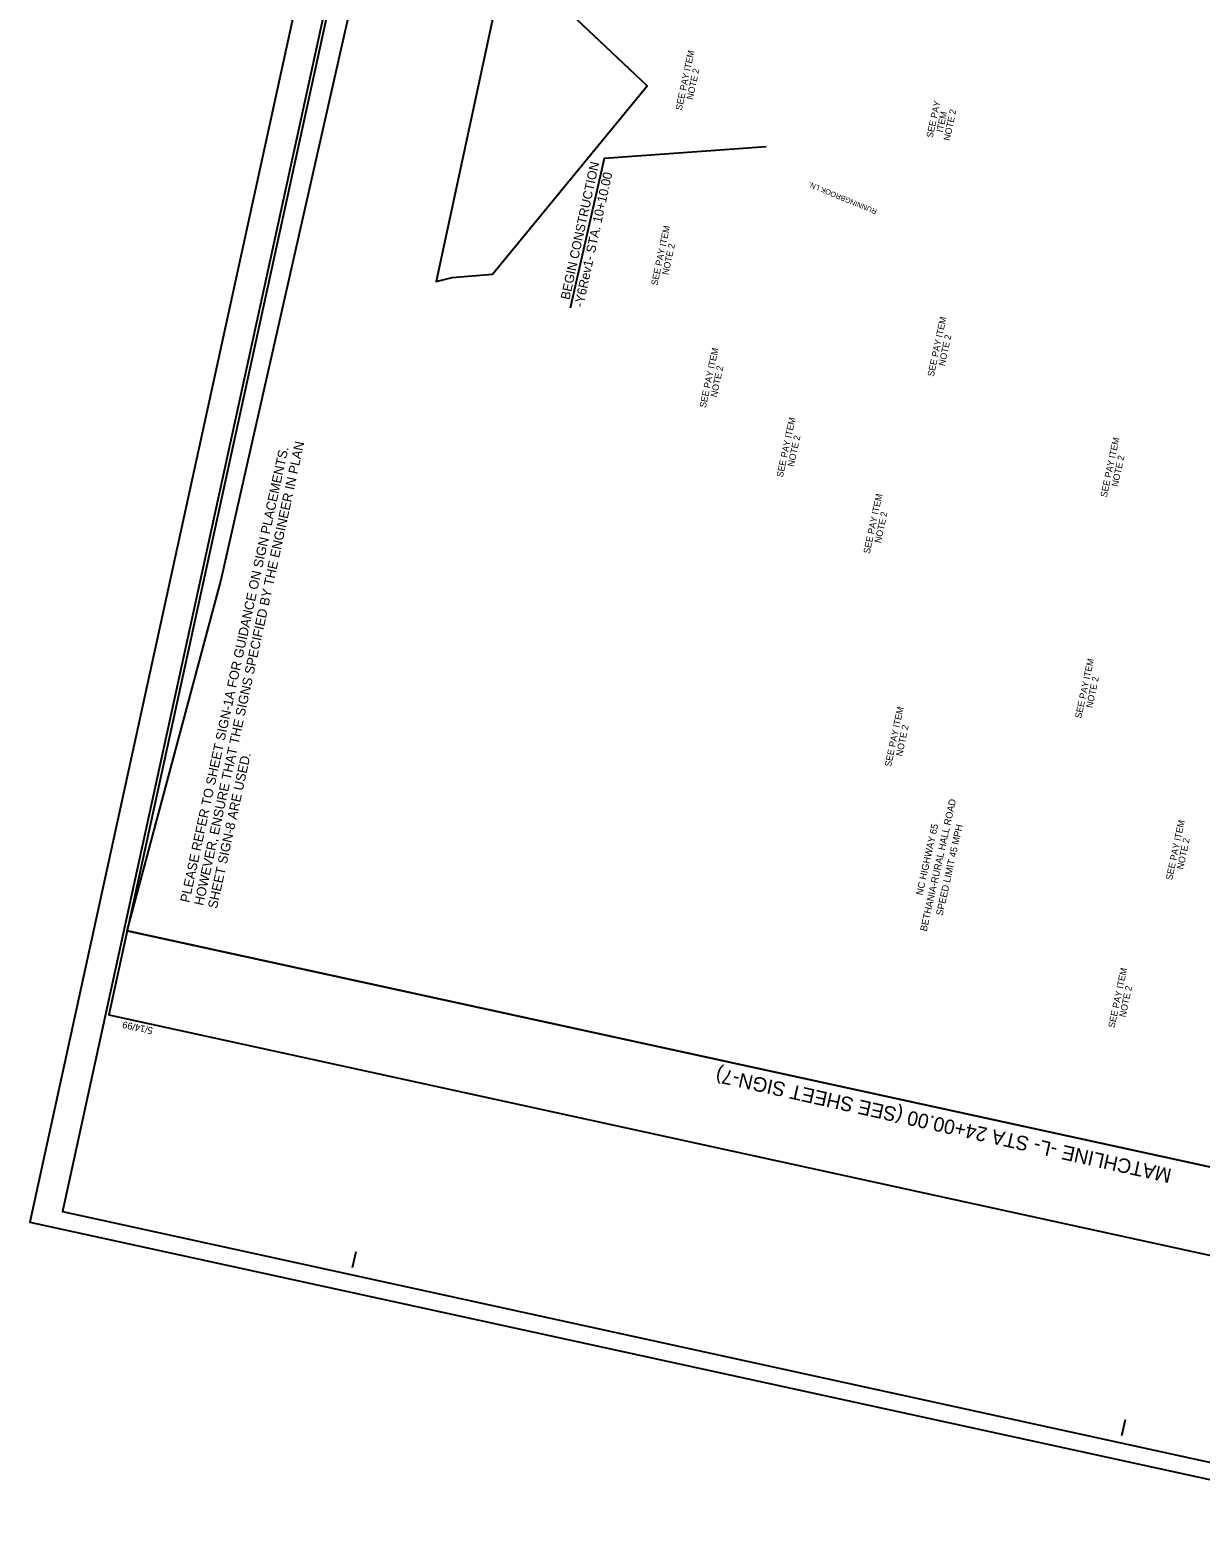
# Model space of a CAD drawing. Extents: x 1615829 to 1617263, y 900664 to 902544.
# Drawn here: x 1615829 to 1616720, y 900664 to 901807 of the extents above; entities that cross this region are included whole.
import ezdxf

# ---------------------------------------------------------------- set-up
doc = ezdxf.new("R2010")
doc.units = 0
for name, color, linetype in [('Default', 7, 'Continuous'), ('Exist PHM ROW shape', 7, 'Continuous'), ('Prop Conc Drive Radius Type', 7, 'Continuous'), ('Prop Conc Island Cover', 7, 'Continuous'), ('Prop Dimension Text', 7, 'Continuous'), ('Prop Lane Arrow CELL', 7, 'Continuous'), ('Prop PHM Concrete Structures Shape', 7, 'Continuous'), ('Prop Shade Medium', 7, 'Continuous'), ('Scratch_Level_2', 7, 'Continuous')]:
    doc.layers.add(name, color=color, linetype=linetype)

msp = doc.modelspace()

# ---------------------------------------------------------------- linework, layer by layer
at = {"layer": 'Exist PHM ROW shape'}
msp.add_lwpolyline([(1616240.6, 901594.9), (1616266.7, 901709), (1616389.9, 901717.9)], dxfattribs=at)
at = {"layer": 'Prop Conc Drive Radius Type'}
msp.add_lwpolyline([(1616850.4, 902379.9), (1617227.5, 902296.2), (1617121.4, 901790.4), (1617088.2, 901641.8), (1617042.4, 901522.3), (1617032.3, 901430.6), (1617021.4, 901334.4), (1616928.8, 900896.8), (1615902.8, 901120.3), (1615974.3, 901386.7), (1616087.7, 901888.9), (1616145.5, 901879.2), (1616184.1, 901827.5), (1616138.4, 901615), (1616150.6, 901618.1), (1616181.3, 901620.7), (1616299.2, 901764.2), (1616120.1, 901933.3), (1616161.3, 902112.5), (1616179.7, 902310.4), (1616356.3, 902284.9), (1616372.4, 902359)], close=True, dxfattribs=at)
at = {"layer": 'Prop Dimension Text'}
msp.add_line((1615902.8, 901120.3), (1616928.8, 900896.8), dxfattribs=at)
at = {"layer": 'Prop PHM Concrete Structures Shape'}
for p, q in [((1615889.1, 901057.4), (1615889.1, 901057.4)), ((1616074.6, 900863.9), (1616077.3, 900876.1)), ((1616660.8, 900735.9), (1616663.5, 900748.1))]:
    msp.add_line(p, q, dxfattribs=at)
msp.add_lwpolyline([(1616208.8, 902521.9), (1615888.9, 901056.4), (1616914.7, 900832.5), (1617234.6, 902298)], close=True, dxfattribs=at)
at = {"layer": 'Prop Shade Medium'}
msp.add_lwpolyline([(1616188, 902543.8), (1615828.8, 900898.6), (1616903.5, 900664), (1617262.7, 902309.2)], close=True, dxfattribs=at)
at = {"layer": 'Scratch_Level_2'}
msp.add_lwpolyline([(1616209, 902534.7), (1615853.6, 900906.5), (1616884.4, 900681.5), (1617239.8, 902309.6)], close=True, dxfattribs=at)

# ---------------------------------------------------------------- texts
at = {"layer": 'Default'}
for s, height, rotation, p in [('SEE PAY ITEM', 5, 77.9223, (1616325.5, 901745.2)), ('NOTE 2', 5, 77.9223, (1616333.9, 901753.2)), ('SEE PAY', 5, 77.9223, (1616516.7, 901724.2)), ('ITEM', 5, 77.9223, (1616524.3, 901728.4)), ('NOTE 2', 5, 77.9223, (1616529.7, 901722)), ('SEE PAY ITEM', 5, 77.9223, (1616306.9, 901611.7)), ('NOTE 2', 5, 77.9223, (1616315.3, 901619.8)), ('SEE PAY ITEM', 5, 77.9223, (1616517.5, 901542.3)), ('NOTE 2', 5, 77.9223, (1616525.9, 901550.4)), ('SEE PAY ITEM', 5, 77.9223, (1616343.8, 901518.5)), ('NOTE 2', 5, 77.9223, (1616352.2, 901526.6)), ('SEE PAY ITEM', 5, 77.9223, (1616402.5, 901465.6)), ('NOTE 2', 5, 77.9223, (1616410.9, 901473.7)), ('PLEASE REFER TO SHEET SIGN-1A FOR GUIDANCE ON SIGN PLACEMENTS.', 7.199, 77.6862, (1615950.2, 901141.5)), ('HOWEVER, ENSURE THAT THE SIGNS SPECIFIED BY THE ENGINEER IN PLAN', 7.199, 77.6862, (1615960.8, 901139.2)), ('SEE PAY ITEM', 5, 77.9223, (1616649.3, 901450.3)), ('NOTE 2', 5, 77.9223, (1616657.8, 901458.4)), ('SEE PAY ITEM', 5, 77.9223, (1616468.7, 901407.4)), ('NOTE 2', 5, 77.9223, (1616477.2, 901415.5)), ('SEE PAY ITEM', 5, 77.9223, (1616629.9, 901281.9)), ('NOTE 2', 5, 77.9223, (1616638.3, 901289.9)), ('SEE PAY ITEM', 5, 77.9223, (1616484.9, 901245.1)), ('NOTE 2', 5, 77.9223, (1616493.4, 901253.1)), ('SHEET SIGN-8 ARE USED.', 7.199, 77.6862, (1615971.3, 901136.9)), ('BETHANIA-RURAL HALL ROAD ', 5.25, 77.409, (1616512.1, 901119.7)), ('NC HIGHWAY 65', 5.25, 77.409, (1616508.9, 901147.2)), ('SPEED LIMIT 45 MPH', 5.25, 77.409, (1616524.2, 901131.6)), ('SEE PAY ITEM', 5, 77.9223, (1616699.1, 901158.8)), ('NOTE 2', 5, 77.9223, (1616707.5, 901166.9)), ('SEE PAY ITEM', 5, 77.9223, (1616655.2, 901046.2)), ('NOTE 2', 5, 77.9223, (1616663.6, 901054.3))]:
    msp.add_text(s, height=height, rotation=rotation, dxfattribs=at).set_placement(p)
at = {"layer": 'Exist PHM ROW shape'}
for s, p in [('BEGIN CONSTRUCTION', (1616239.9, 901600.8)), ('-Y6Rev1- STA. 10+10.00', (1616250.3, 901595.1))]:
    msp.add_text(s, height=7, rotation=77.6862, dxfattribs=at).set_placement(p)
at = {"layer": 'Prop Conc Island Cover'}
msp.add_text('RUNNINGBROOK LN.', height=4, rotation=157.5812, dxfattribs=at).set_placement((1616474.6, 901669.8))
at = {"layer": 'Prop Lane Arrow CELL'}
msp.add_text('MATCHLINE -L- STA 24+00.00 (SEE SHEET SIGN-7)', height=11, rotation=167.4336, dxfattribs=at).set_placement((1616699.4, 900938.9))
at = {"layer": 'Prop PHM Concrete Structures Shape'}
msp.add_text('5/14/99', height=5.25, rotation=167.6862, dxfattribs=at).set_placement((1615922.8, 901046.7))

doc.saveas('drawing.dxf')
